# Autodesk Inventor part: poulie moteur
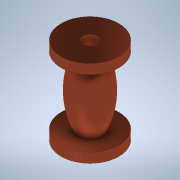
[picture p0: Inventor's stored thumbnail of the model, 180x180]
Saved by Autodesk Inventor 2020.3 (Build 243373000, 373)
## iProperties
Created: 2020-09
Part Number: poulie moteur
Material: Bronze, étain doux
Document SubType Name: Modeling
Designer: ficho
Density: 8.874 g/cm^3
Appearance: Cuivre - Poli
Author: ficho
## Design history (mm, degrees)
sketch "Esquisse1"
  geometry: L1 (0, 0)-(3, 0); L2 (3, 9)-(0, 9); L3 (0, 9)-(0, 0); L4 (3, 8)-(1.25, 8); L5 (3, 1)-(1.25, 1); L6 (3, 0)-(3, 1); L7 (3, 8)-(3, 9); A1 r 8.542 centre (-6.542, 4.5) between (1.25, 1) and (1.25, 8)
  constraints: 14 end point, 3 parallel, 3 perpendicular, 2 horizontal, 2 point on circle, 1 centre point
  dimensions: "d0" = 3 distance of L2.end L2.start; "d1" = 9 distance of L2.start L1.end; "d2" = 1 distance between parallel lines of L4 L2; "d3" = 1 distance between parallel lines of L1 L5 (= d2)
revolve "Révolution1" sketch "Esquisse1" stored, may be unused: angle "d6" = 90 deg
sketch "Esquisse2"
  geometry: 1 further point
hole "Perçage1" sketch "Esquisse2" at (0, 0) diameter "d7" = 1.5; stored, may be unused: countersink angle "d11" = 90 deg, drill point angle "d13" = 118 deg; dims "d8" = 6, "d9" = 4, "d10" = 2, "d12" = 8
node "Solide1"
other parameters: "d5" = 1.25
